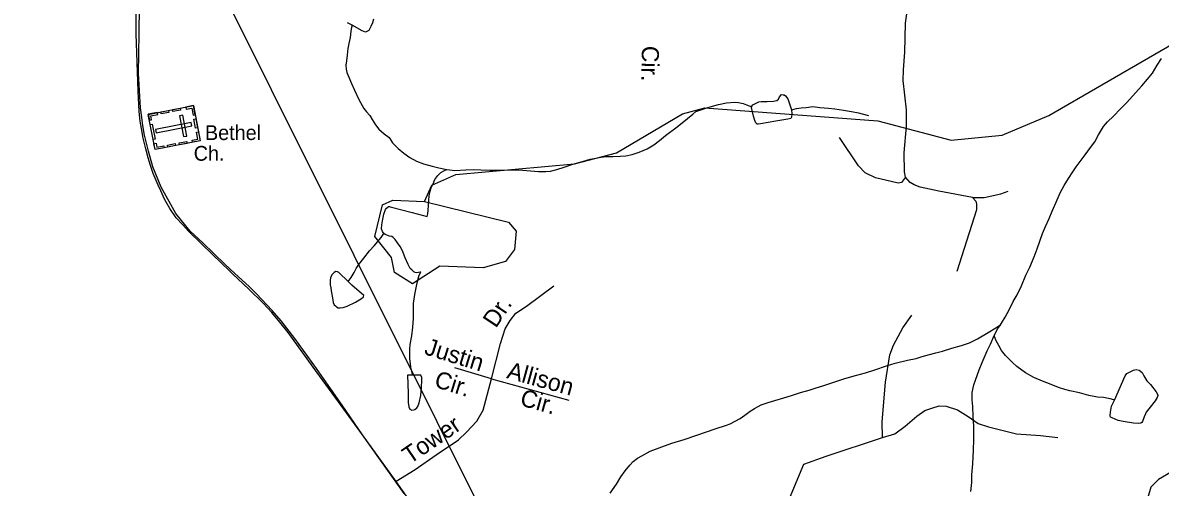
# Model space of a CAD drawing. Extents: x 2082433 to 2279600, y 546599 to 755198.
# Drawn here: x 2103425 to 2109736, y 625253 to 627832 of the extents above; entities that cross this region are included whole.
import ezdxf

# ---------------------------------------------------------------- set-up
doc = ezdxf.new("R2010")
doc.units = 0
for name, color, linetype in [('Exist Boundary Political CountyLine', 7, 'Continuous'), ('Exist Boundary Political Fire Districts', 7, 'Continuous'), ('Exist Cultural Cemetery CELL', 7, 'Continuous'), ('Exist Cultural Cemetery Label', 7, 'Continuous'), ('Exist Hydrographic Creek Single Shore', 7, 'Continuous'), ('Exist Hydrographic Misc Water Feature', 7, 'Continuous'), ('Exist Hydrographic Pond Under 1500 Sq Ft', 7, 'Continuous'), ('Exist Road Non-System Type 51', 7, 'Continuous'), ('Exist Road Non-System Type 51 Label', 7, 'Continuous'), ('Exist Road Secondary Type 51 Attributed', 7, 'Continuous'), ('Map Preparation Inset Cut Line', 7, 'Continuous')]:
    doc.layers.add(name, color=color, linetype=linetype)

msp = doc.modelspace()

# ---------------------------------------------------------------- linework, layer by layer
at = {"layer": 'Exist Boundary Political CountyLine'}
msp.add_lwpolyline([(2105542.3, 625219.4), (2105309.9, 625544.1), (2105197.2, 625708.6), (2105055.8, 625913.2), (2104934.5, 626079.1), (2104859, 626178.2), (2104808.3, 626235.2), (2104721.7, 626326.8), (2104683.3, 626366.4), (2104600.4, 626441.9), (2104547.2, 626491.5), (2104423.7, 626610.7), (2104355, 626675.9), (2104329.4, 626705.7), (2104273.7, 626773.8), (2104193.3, 626919.9), (2104147.5, 627032.6), (2104122.8, 627119.2), (2104109.1, 627171.2), (2104100.6, 627207.6), (2104091.4, 627262.4), (2104085.3, 627306.5), (2104078.6, 627359.7), (2104067.1, 627550.1), (2104072, 627771.8), (2104078.9, 628371.7)], dxfattribs=at)
at = {"layer": 'Exist Boundary Political Fire Districts'}
for points in [[(2104055.4, 627770.5), (2104053, 628118.1)], [(2105685, 625016.5), (2105497.8, 625285.6), (2105309.9, 625544.1), (2105192, 625706.9), (2105036.8, 625920.9), (2104897, 626112.5), (2104850.8, 626170.6), (2104806.3, 626223.3), (2104758.7, 626274.6), (2104680, 626352.6), (2104589, 626437.8), (2104573.2, 626454.4), (2104480.3, 626543.8), (2104415.5, 626607.3), (2104346.8, 626672.5), (2104310.7, 626711.8), (2104277.1, 626749.3), (2104242, 626800.9), (2104211.7, 626852), (2104191, 626898.5), (2104176.8, 626930.5), (2104148.7, 626995.3), (2104133.5, 627039.3), (2104121.4, 627082.5), (2104107.5, 627132.5), (2104092.7, 627191), (2104083.5, 627245.8), (2104077.6, 627286.5), (2104070.8, 627339.7), (2104066.1, 627452.9), (2104055.4, 627770.5)]]:
    msp.add_lwpolyline(points, dxfattribs=at)
at = {"layer": 'Exist Cultural Cemetery CELL'}
for points in [[(2104371.8, 627372.1), (2104409.6, 627176.7), (2104159.6, 627128.4), (2104121.8, 627323.8)], [(2104329.3, 627363.9), (2104331.5, 627352.8), (2104363.1, 627358.9), (2104370.7, 627319.1), (2104381.7, 627321.2), (2104371.8, 627372.1)], [(2104128.1, 627291.4), (2104139.4, 627293.5), (2104135.2, 627315.1), (2104174.9, 627322.8), (2104172.8, 627333.7), (2104121.9, 627323.9)], [(2104190.5, 627337.1), (2104233, 627345.3), (2104235.2, 627334.2), (2104192.6, 627326)], [(2104256.5, 627349.9), (2104299, 627358.1), (2104301.2, 627346.9), (2104258.6, 627338.7)], [(2104312.7, 627319.1), (2104294.4, 627315.6), (2104316.7, 627200), (2104335.1, 627203.5)], [(2104144, 627269.6), (2104160.1, 627186.3), (2104148.9, 627184.1), (2104132.8, 627267.4)], [(2104363.7, 627259.5), (2104360.2, 627277.9), (2104161.1, 627239.4), (2104164.6, 627221.1)], [(2104385.9, 627299.4), (2104395.7, 627248.5), (2104384.5, 627246.4), (2104374.7, 627297.2)], [(2104367, 627168.4), (2104364.9, 627179.5), (2104396.5, 627185.6), (2104388.8, 627225.4), (2104399.7, 627227.5), (2104409.6, 627176.6)], [(2104153.3, 627160.9), (2104164.6, 627163.1), (2104168.7, 627141.5), (2104208.4, 627149.1), (2104210.5, 627138.2), (2104159.6, 627128.4)], [(2104228.4, 627153.2), (2104270.9, 627161.4), (2104273.1, 627150.3), (2104230.5, 627142)], [(2104293.1, 627165.7), (2104335.6, 627173.9), (2104337.8, 627162.7), (2104295.3, 627154.5)]]:
    msp.add_lwpolyline(points, close=True, dxfattribs=at)
at = {"layer": 'Exist Hydrographic Creek Single Shore'}
msp.add_lwpolyline([(2105653.4, 626840.1), (2105694.4, 626931), (2105828.5, 626990.7), (2106486.5, 627049.5), (2106719.5, 627110.4), (2107085.5, 627326.1), (2107209.5, 627359.7), (2108168.4, 627287.7), (2108576.4, 627181), (2108859.4, 627208.1), (2109117.6, 627317.7), (2109999.5, 627828), (2110390.6, 627944.7), (2110673.5, 628129.3), (2111454.6, 628848.3), (2111719.5, 629357.9)], dxfattribs=at)
at = {"layer": 'Exist Hydrographic Misc Water Feature'}
for points in [[(2105252.9, 627818.5), (2105248.8, 627806.5), (2105245.1, 627784.7), (2105241.6, 627750.4), (2105235.1, 627716.5), (2105229.5, 627688.6), (2105225.7, 627652.6), (2105222.2, 627620.3), (2105217.7, 627596.7), (2105219.9, 627574.4), (2105223.8, 627556.4), (2105233.9, 627530.5), (2105250.1, 627494.8), (2105266.5, 627458.7), (2105290.7, 627406.8), (2105318.3, 627356.7), (2105332.5, 627337.2), (2105350.5, 627317), (2105364.7, 627295), (2105382.9, 627265), (2105400.8, 627241.3), (2105430.9, 627215.2), (2105457.4, 627195.4), (2105477, 627165.6), (2105507.4, 627133.5), (2105539.6, 627107.5), (2105573.4, 627083.7), (2105609.1, 627063.7), (2105649.3, 627049.9), (2105697.3, 627036.2), (2105733.4, 627026.3), (2105777.7, 627018.4)], [(2105252.9, 627818.5), (2105227.3, 627832.5)], [(2105370.8, 627852.9), (2105365.1, 627831.1), (2105357.1, 627810.8), (2105345.4, 627789), (2105334.9, 627782.9), (2105327.4, 627780.8), (2105309.3, 627786.8), (2105252.9, 627818.5)], [(2108849.1, 626154.3), (2108855.5, 626164.3), (2108875.2, 626198.2), (2108897.1, 626238.2), (2108920.9, 626284.1), (2108943, 626322.2), (2108966.6, 626372.5), (2108990.4, 626430.6), (2109012.1, 626474.7), (2109036.3, 626532.7), (2109053.8, 626576.7), (2109068.1, 626618.8), (2109083.5, 626662.6), (2109099.7, 626700.8), (2109119.4, 626744.8), (2109137.4, 626787.1), (2109159.4, 626836.9), (2109180.7, 626888.8), (2109202.6, 626928.9), (2109226.4, 626967.1), (2109250.6, 627005.2), (2109270.1, 627033.1), (2109292.2, 627061.3), (2109320.3, 627099.3), (2109350.1, 627139.4), (2109372.4, 627171.7), (2109394, 627209.4), (2109410.2, 627237.4), (2109421.6, 627255.5), (2109443.4, 627281.8), (2109477.6, 627313.9), (2109515.3, 627354), (2109551.6, 627390), (2109599.2, 627443.9), (2109634.9, 627482.3), (2109664.8, 627518.4), (2109692.5, 627552.3), (2109718.5, 627596.7), (2109742.3, 627634.4)], [(2107469.7, 627365.6), (2107470.2, 627369.7), (2107475.7, 627375.7), (2107509.7, 627393.7), (2107522, 627395.9), (2107533.9, 627395.7), (2107556.1, 627396), (2107590.1, 627396.1), (2107609.8, 627400), (2107618, 627408.1), (2107623.9, 627420.2), (2107635.6, 627434.2), (2107643.6, 627432.2), (2107649.6, 627432.1), (2107657.6, 627426), (2107669.7, 627410), (2107679.9, 627382.1), (2107690, 627348.1)], [(2107181.9, 627346.8), (2107226.1, 627362.7), (2107285.8, 627378.9), (2107329.7, 627387.2), (2107375.8, 627391.2), (2107395.9, 627389.3), (2107421.8, 627383.5), (2107440, 627377.5), (2107456, 627371.4), (2107469.7, 627365.6)], [(2105777.7, 627018.4), (2105823.4, 627012.6), (2105883.3, 627014.9), (2105923.7, 627016.9), (2105967.5, 627015.1), (2106019.4, 627013.3), (2106069.6, 627013.4), (2106125.2, 627015.6), (2106167.5, 627015.7), (2106197.2, 627013.6), (2106287.4, 627006.1), (2106327.2, 627006.1), (2106353.6, 627008.2), (2106389.3, 627018.2), (2106429.1, 627030.4), (2106477.3, 627046.7), (2106531.4, 627062.8), (2106572.8, 627074.7), (2106595.4, 627079.1), (2106623.1, 627085), (2106659.2, 627089.3), (2106699, 627089.3), (2106738.9, 627091.4), (2106770.7, 627093.5), (2106806.8, 627101.4), (2106845.2, 627113.9), (2106888.8, 627132), (2106926.6, 627153.8), (2106958.8, 627178.2), (2106990.5, 627206.2), (2107056.4, 627254.2), (2107114.2, 627300.6), (2107142.1, 627324.4), (2107160.1, 627338.7), (2107181.9, 627346.8)], [(2107690, 627348.1), (2107692.4, 627326.2), (2107690.2, 627308.4), (2107685.9, 627300.5), (2107669.9, 627296.4), (2107604.1, 627286.1), (2107517.9, 627272), (2107506, 627269.7), (2107500.1, 627269.8), (2107496.2, 627273.6), (2107492.1, 627277.5), (2107486.1, 627289.7), (2107480.2, 627313.7), (2107467.9, 627361.5), (2107469.7, 627365.6)], [(2107690, 627348.1), (2107717.9, 627356.5), (2107743.9, 627360.2), (2107772, 627362.5), (2107807.9, 627366.7), (2107848.1, 627362.7), (2107895.8, 627358.7), (2107930.1, 627354.7), (2107979.7, 627347.2), (2108024, 627339.3), (2108061.7, 627331.6), (2108081.8, 627327.3), (2108118.1, 627317.4)], [(2105668.4, 626756.3), (2105672.5, 626772.2), (2105674.1, 626792.3), (2105676.2, 626817.9), (2105678.4, 626846), (2105679.6, 626872.2), (2105685.8, 626896.4), (2105692.1, 626916.1), (2105701.8, 626938.2), (2105711.6, 626962.2), (2105727.6, 626984.1), (2105745.7, 627000.5), (2105765.6, 627012.5), (2105777.7, 627018.4)], [(2105428.7, 626661.6), (2105420.9, 626673.3), (2105416.4, 626687.4), (2105416.6, 626711.2), (2105420.7, 626733.3), (2105428.4, 626769.5), (2105438.3, 626795.6), (2105444.2, 626803.6), (2105450, 626807.6), (2105454.1, 626811.4), (2105460, 626811.3), (2105463.9, 626809.5), (2105586.1, 626778), (2105668.4, 626756.3)], [(2105231.6, 626394.9), (2105235.5, 626402.8), (2105247.6, 626418.8), (2105263.4, 626444.9), (2105275.1, 626467), (2105289.4, 626489.2), (2105317.1, 626525.2), (2105349.3, 626565.3), (2105374.7, 626593.4), (2105414.7, 626639.3), (2105428.7, 626661.6)], [(2105633.3, 626448.1), (2105629.4, 626448.3), (2105611.4, 626444.1), (2105603.2, 626446.1), (2105595.4, 626450.2), (2105583.5, 626460.1), (2105574.9, 626467.8), (2105563.4, 626489.9), (2105547.2, 626528), (2105533, 626565.9), (2105518.7, 626589.9), (2105505.1, 626609.8), (2105491, 626629.8), (2105480.7, 626639.5), (2105472.3, 626645.6), (2105460.6, 626647.4), (2105444.6, 626653.4), (2105436.4, 626657.5), (2105428.7, 626661.6)], [(2105231.6, 626394.9), (2105179.5, 626446.6), (2105171.3, 626448.7), (2105161.5, 626450.6), (2105153.1, 626446.5), (2105141.4, 626434.5), (2105133.6, 626418.7), (2105131.5, 626400.7), (2105131.5, 626376.4), (2105133.8, 626360.7), (2105135.6, 626344.6), (2105143.8, 626304.8), (2105148.1, 626278.6), (2105153.7, 626266.8), (2105160, 626260.6), (2105166.2, 626254.7), (2105175.8, 626248.9), (2105186.1, 626248.9), (2105202.1, 626251), (2105225.9, 626258.7), (2105271.8, 626280.9), (2105305.6, 626301), (2105315.9, 626311.2), (2105317.7, 626317.4), (2105251.7, 626374.9), (2105231.6, 626394.9)], [(2105587.2, 625876.3), (2105585.3, 625890), (2105580.6, 625908.1), (2105578.8, 625924.3), (2105572.8, 625966.1), (2105572.4, 625994.1), (2105572.6, 626020.1), (2105574.9, 626046.1), (2105584.5, 626094.1), (2105589.8, 626142), (2105594.1, 626190), (2105593.9, 626230.1), (2105593.9, 626273.9), (2105599.9, 626324.2), (2105613.4, 626388.2), (2105625.1, 626430.2), (2105633.3, 626448.1)], [(2106685, 625219.8), (2106718.8, 625269.8), (2106744.1, 625311.8), (2106768.3, 625343.9), (2106792.7, 625375.8), (2106812.1, 625396), (2106835.9, 625414.3), (2106859.9, 625428.1), (2106906.1, 625454.4), (2106971.7, 625478.5), (2107025.6, 625498.7), (2107094.1, 625518.8), (2107165.7, 625543.3), (2107267.4, 625577.3), (2107329.5, 625597.6), (2107349.4, 625605.4), (2107373.2, 625617.7), (2107405.6, 625635.9), (2107431, 625653.9), (2107461.1, 625676.1), (2107485.1, 625690), (2107522.9, 625710.2), (2107561, 625724.3), (2107598.7, 625734.4), (2107646.9, 625750.6), (2107690.6, 625762.7), (2107741, 625779), (2107788.8, 625792.8), (2107826.5, 625805), (2107864.7, 625817.1), (2107902.8, 625829.1), (2107936.6, 625841.4), (2107986.5, 625857.4), (2108046.3, 625873.9), (2108100.5, 625888), (2108152.4, 625906.1), (2108218.2, 625928.2), (2108266.4, 625942.3), (2108334, 625958.5), (2108382, 625968.6), (2108415.6, 625979), (2108456, 625991.2), (2108491.7, 625999.1), (2108527.8, 626009), (2108579.9, 626025.5), (2108633.6, 626041.3), (2108677.5, 626055.7), (2108721.6, 626077.8), (2108781.3, 626111.8), (2108823.5, 626137.9), (2108849.1, 626154.3)], [(2108815.3, 626096.1), (2108835.6, 626134), (2108849.1, 626154.3)], [(2108686.1, 625229.9), (2108690.2, 625280), (2108691.6, 625322), (2108695.7, 625383.8), (2108699.4, 625459.9), (2108701.5, 625518), (2108701.1, 625591.9), (2108699, 625645.7), (2108696.4, 625701.7), (2108692.7, 625737.9), (2108692.9, 625779.7), (2108702.3, 625822), (2108710.5, 625848), (2108732, 625906), (2108747.6, 625945.7), (2108775.7, 626010), (2108793.6, 626047.9), (2108815.3, 626096.1)], [(2109482.5, 625736.4), (2109478.6, 625738.2), (2109458.3, 625744.1), (2109440.3, 625748), (2109420.6, 625751.9), (2109388.6, 625753.9), (2109340.4, 625763.5), (2109288.4, 625777.5), (2109234.2, 625789.4), (2109206.3, 625795.2), (2109172.1, 625807.3), (2109130.3, 625823), (2109082.1, 625842.8), (2109033.9, 625862.7), (2108988.2, 625888.7), (2108940, 625924.4), (2108916.2, 625946.6), (2108893.8, 625968.2), (2108877.8, 625984.4), (2108855.7, 626012.2), (2108839.9, 626040.1), (2108825.5, 626066.2), (2108815.3, 626096.1)], [(2105587.2, 625876.3), (2105559.3, 625876.1), (2105563.4, 625776.1), (2105563.6, 625724.1), (2105567.7, 625700), (2105573.4, 625686.1), (2105583.9, 625682.1), (2105593.5, 625682.3), (2105601.5, 625684.3), (2105611.8, 625694.1), (2105617.3, 625702.2), (2105623.7, 625722.3), (2105633.3, 625762.3), (2105637.6, 625808.2), (2105639.2, 625846.1), (2105638.8, 625862.4), (2105633.1, 625876.2), (2105587.2, 625876.3)], [(2109482.5, 625736.4), (2109541.8, 625872.2), (2109550.2, 625884.3), (2109587.9, 625902.5), (2109601.9, 625906.5), (2109619.9, 625902.5), (2109635.7, 625890.8), (2109646, 625872.6), (2109662.2, 625844.6), (2109681.8, 625823), (2109714.2, 625782.8), (2109722.2, 625767), (2109722.4, 625762.9), (2109718.3, 625751), (2109708.1, 625733), (2109680.2, 625698.7), (2109658.7, 625670.8), (2109654.4, 625660.9), (2109646.6, 625644.6), (2109638.6, 625618.7), (2109634.5, 625612.8), (2109628.7, 625608.8), (2109614.8, 625606.8), (2109587.1, 625608.6), (2109530.9, 625618.3), (2109503, 625624.2), (2109468.8, 625638.3), (2109460.6, 625642.4), (2109458.7, 625652.4), (2109460.6, 625670.3), (2109466.5, 625704.3), (2109482.5, 625736.4)]]:
    msp.add_lwpolyline(points, dxfattribs=at)
at = {"layer": 'Exist Hydrographic Pond Under 1500 Sq Ft'}
msp.add_lwpolyline([(2105653.4, 626840.1), (2106120.5, 626725.6), (2106162.3, 626675.6), (2106154.3, 626574), (2106104.5, 626506.1), (2105979.4, 626472.5), (2105738.5, 626480.7), (2105588.4, 626382.1), (2105488.3, 626446.5), (2105471.5, 626528.8), (2105379.4, 626645.5), (2105420.4, 626821.8), (2105478.5, 626846.9), (2105653.4, 626840.1)], dxfattribs=at)
at = {"layer": 'Exist Road Non-System Type 51'}
for q in [(2105822.8, 625916.9), (2106454.2, 625736.8)]:
    msp.add_line((2106025.6, 625854.8), q, dxfattribs=at)
for points in [[(2108323.6, 626974.4), (2108316.8, 627004.3), (2108314.5, 627109.8), (2108328.2, 627258.9), (2108328.2, 627348.4), (2108319.1, 627431), (2108309.9, 627511.3), (2108312.2, 627571), (2108319.1, 627669.6), (2108323.6, 627830.3), (2108342, 627957.6), (2108360.4, 628059.7), (2108374.1, 628289.1), (2108385.6, 628503.7), (2108390.2, 628542.7), (2108381, 628590.9)], [(2108323.6, 626974.4), (2108300.7, 626944.6), (2108282.3, 626942.3), (2108243.3, 626951.5), (2108156.2, 626972.1), (2108098.8, 626999.7), (2108062.1, 627038.7), (2107956.5, 627194.7)], [(2108695.3, 626862), (2108507.2, 626896.4), (2108404, 626919.4), (2108371.8, 626933.1), (2108348.9, 626944.6), (2108323.6, 626974.4)], [(2108695.3, 626862), (2108713.7, 626841.4), (2108716, 626825.3), (2108716, 626793.2), (2108608.2, 626451.3)], [(2108695.3, 626862), (2108759.6, 626862), (2108851.4, 626882.7), (2108892.7, 626896.4)], [(2106025.6, 625854.8), (2106075.3, 626051.5), (2106102.2, 626132.2), (2106129.1, 626179.8), (2106160.2, 626219.2), (2106220.2, 626258.5), (2106371.3, 626372.4)], [(2108195.2, 625528.9), (2108192.9, 625617.3), (2108211.2, 625837.5), (2108236.5, 625989), (2108257.1, 626041.7), (2108307.6, 626138.1), (2108358.1, 626208.1)], [(2105496.1, 625287.9), (2105603.3, 625351.8), (2105719.3, 625432.5), (2105843.5, 625517.4), (2105886.9, 625558.8), (2105944.9, 625620.9), (2105980.1, 625680.9), (2106025.6, 625854.8)], [(2108195.2, 625528.9), (2108264, 625549.6), (2108321.4, 625593.2), (2108385.6, 625648.2), (2108429.2, 625680.4), (2108468.2, 625691.8), (2108509.5, 625705.6), (2108548.5, 625703.3), (2108610.5, 625682.7), (2108670.1, 625646), (2108725.2, 625606.9), (2108782.5, 625588.6), (2108938.6, 625549.6), (2109071.6, 625540.4), (2109168, 625528.9)], [(2107023.9, 623667.4), (2107247.6, 624158), (2107759.2, 625382.1), (2107883.1, 625425.7), (2108195.2, 625528.9)]]:
    msp.add_lwpolyline(points, dxfattribs=at)
at = {"layer": 'Exist Road Secondary Type 51 Attributed'}
msp.add_lwpolyline([(2113829.9, 627219.7), (2113543.1, 627177.5), (2113243.1, 627141.6), (2112875.2, 627092.3), (2112766.2, 627063.6), (2112659.5, 627015.8), (2112188.1, 626730.8), (2111855.7, 626526.1), (2111588.6, 626364.6), (2111289.1, 626181.4), (2111201.3, 626114.7), (2111091, 625999.1), (2110931.4, 625810.4), (2110857.4, 625745.1), (2110759.6, 625687), (2110488.7, 625581.1), (2109961.6, 625400.4), (2109801.7, 625339.9), (2109726.1, 625296.9), (2109683.1, 625253.9), (2109624.1, 625049.8)], dxfattribs=at)
at = {"layer": 'Map Preparation Inset Cut Line'}
msp.add_lwpolyline([(2125488.3, 585979.7), (2103425.3, 630228.2), (2125488.3, 630228.2)], close=True, dxfattribs=at)

# ---------------------------------------------------------------- texts
at = {"layer": 'Exist Cultural Cemetery Label'}
for s, p in [('Bethel ', (2104436.4, 627181.1)), (' Ch.', (2104343.3, 627066.2))]:
    msp.add_text(s, height=82.02, dxfattribs=at).set_placement(p)
at = {"layer": 'Exist Road Non-System Type 51 Label'}
for s, rotation, p in [('Cir.', 268.83082, (2106860.6, 627704.9)), ('Dr.', 56.32875, (2106050.4, 626132.7)), ('Justin', 342.88574, (2105648.4, 625993.1)), ('Allison', 344.62775, (2106105.6, 625860.4)), ('Cir.', 342.88574, (2105702.8, 625812.1)), ('Cir.', 344.62775, (2106178.7, 625709.2)), ('Tower', 34.31507, (2105573, 625379.3))]:
    msp.add_text(s, height=95, rotation=rotation, dxfattribs=at).set_placement(p)

doc.saveas('drawing.dxf')
